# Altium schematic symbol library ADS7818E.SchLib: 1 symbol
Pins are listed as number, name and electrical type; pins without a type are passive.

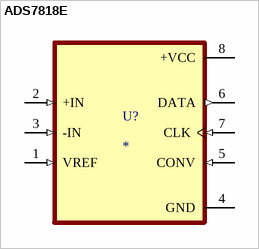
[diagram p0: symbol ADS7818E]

## ADS7818E
designator U?
MP: ADS7818P
footprint ADS7818E
pins: 1 VREF (in), 2 +IN (in), 3 -IN (in), 4 GND (power), 5 CONV (in), 6 DATA (out), 7 CLK (in), 8 +VCC (power)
